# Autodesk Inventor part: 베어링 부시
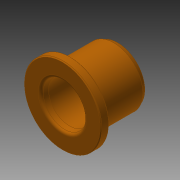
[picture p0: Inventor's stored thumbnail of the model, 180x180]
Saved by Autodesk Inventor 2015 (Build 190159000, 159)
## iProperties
Created: 2022-03
Part Number: 베어링 부시
Material: 황동, 연질
Document SubType Name: Modeling
Designer: mdu-01
Density: 1 g/cm^3
Appearance: 주황색
Author: mdu-01
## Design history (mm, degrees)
sketch "스케치1"
  geometry: L1 (0, 0)-(0, -20); L2 (7.941, 0)-(14, 0); L3 (14, 0)-(14, -3); L4 (14, -3)-(10.5, -3); L5 (10.5, -3)-(10.5, -18.6); L6 (9.844, -20)-(7.606, -20); L7 (7.5, -2.5)-(7.5, -19.4); L8 (7.5, -2.5)-(7.941, 0); L9 (7.5, -19.4)-(7.606, -20); L10 (10.5, -18.6)-(9.844, -20)
  constraints: 20 end point, 3 perpendicular, 2 horizontal alignment, 2 parallel, 1 horizontal, 1 vertical
  dimensions: "d0" = 21 diameter of L5 L1; "d2" = 28 diameter of L3 L1; "d3" = 20 distance of L1.start L1.end; "d4" = 3 distance of L2.end L3.end; "d5" = 15 diameter of L7 L1; "d6" = 10 deg angle of L7 L9; "d7" = 0.6 distance from line of L7.end L6; "d8" = 1.4 vertical distance of L5.end L6.start; "d9" = 25.0978 deg angle of L5 L10; "d10" = 10 deg angle of L7 L8; "d11" = 2.5 vertical distance of L7.start L2.start
revolve "회전1" sketch "스케치1" stored, may be unused: angle "d12" = 90 deg
chamfer "모따기1" distance "d13" = 0.3; stored, may be unused: second distance "d14" = 2, angle "d15" = 45 deg
fillet "모깎기1" dims "d16" = 0.3, "d17" = 1
node "솔리드1"
